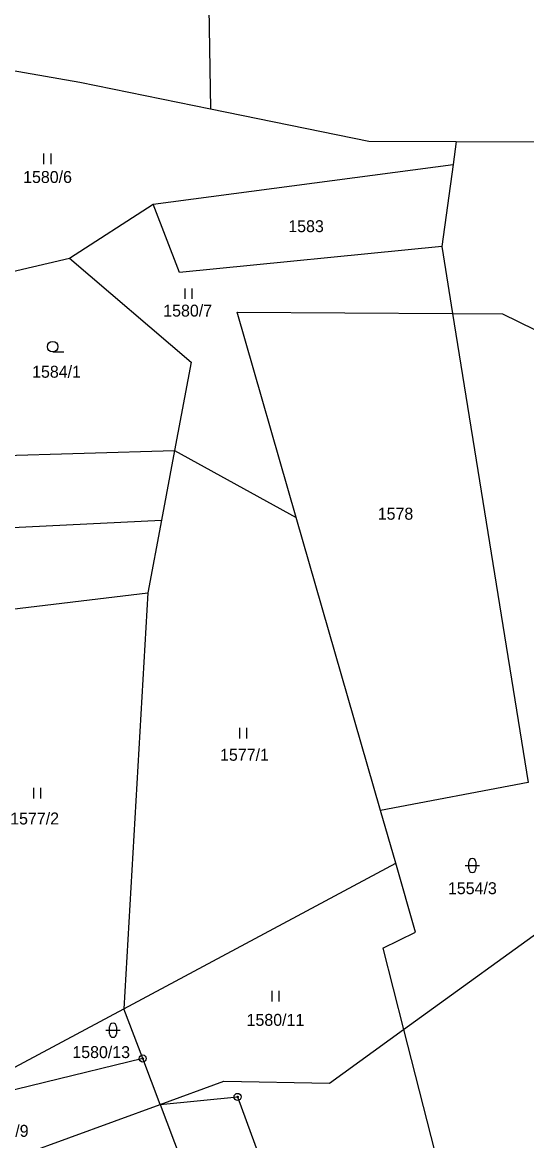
# Model space of a CAD drawing. Extents: x -445050 to -440454, y -1134563 to -1129741.
# Drawn here: x -442586.8 to -442515, y -1132305.3 to -1132146.1 of the extents above; entities that cross this region are included whole.
import ezdxf

# ---------------------------------------------------------------- set-up
doc = ezdxf.new("R2010")
doc.units = 0
for name, color, linetype in [('Vrstva 1', 7, 'Continuous'), ('Vrstva 18', 7, 'Continuous'), ('Vrstva 24', 7, 'Continuous'), ('Vrstva 25', 7, 'Continuous')]:
    doc.layers.add(name, color=color, linetype=linetype)

msp = doc.modelspace()

# ---------------------------------------------------------------- linework, layer by layer
at = {"layer": 'Vrstva 1'}
msp.add_line((-442525.04, -1132163.08), (-442509.94, -1132163.14), dxfattribs=at)
for points in [[(-442560.28, -1132144.07), (-442560.02, -1132158.43)], [(-442612.12, -1132148.81), (-442578.64, -1132154.62)], [(-442578.64, -1132154.62), (-442560.02, -1132158.43)], [(-442560.02, -1132158.43), (-442537.49, -1132163.03)], [(-442537.49, -1132163.03), (-442525.04, -1132163.08)], [(-442525.04, -1132163.08), (-442525.48, -1132166.35)], [(-442568.21, -1132172), (-442525.48, -1132166.35)], [(-442525.48, -1132166.35), (-442527.08, -1132178.05)], [(-442580.11, -1132179.71), (-442568.21, -1132172)], [(-442564.44, -1132181.73), (-442568.21, -1132172)], [(-442527.08, -1132178.05), (-442564.44, -1132181.73)], [(-442527.08, -1132178.05), (-442525.55, -1132187.56)], [(-442593.76, -1132182.86), (-442580.11, -1132179.71)], [(-442580.11, -1132179.71), (-442562.79, -1132194.5)], [(-442547.82, -1132216.6), (-442556.25, -1132187.37)], [(-442556.25, -1132187.37), (-442525.55, -1132187.56)], [(-442525.55, -1132187.56), (-442518.42, -1132187.61)], [(-442525.55, -1132187.56), (-442514.77, -1132254.31)], [(-442518.42, -1132187.61), (-442507.11, -1132193.16)], [(-442562.79, -1132194.5), (-442565.15, -1132207.06)], [(-442603.8, -1132208.19), (-442565.15, -1132207.06)], [(-442565.15, -1132207.06), (-442567.01, -1132216.98)], [(-442565.15, -1132207.06), (-442547.82, -1132216.6)], [(-442535.8, -1132258.33), (-442547.82, -1132216.6)], [(-442616.35, -1132219.39), (-442567.01, -1132216.98)], [(-442567.01, -1132216.98), (-442568.95, -1132227.32)], [(-442590.75, -1132229.95), (-442568.95, -1132227.32)], [(-442568.95, -1132227.32), (-442572.37, -1132286.52)], [(-442514.77, -1132254.31), (-442535.8, -1132258.33)], [(-442533.64, -1132265.82), (-442535.8, -1132258.33)], [(-442572.37, -1132286.52), (-442533.64, -1132265.82)], [(-442530.81, -1132275.65), (-442533.64, -1132265.82)], [(-442532.53, -1132289.48), (-442509.81, -1132273.06)], [(-442535.49, -1132277.89), (-442530.81, -1132275.65)], [(-442535.49, -1132277.89), (-442532.53, -1132289.48)], [(-442596.72, -1132299.53), (-442572.37, -1132286.52)], [(-442569.69, -1132293.61), (-442572.37, -1132286.52)], [(-442543.07, -1132297.1), (-442532.53, -1132289.48)], [(-442532.53, -1132289.48), (-442515.83, -1132354.84)], [(-442569.69, -1132293.61), (-442611.76, -1132303.88)], [(-442567.21, -1132300.16), (-442569.69, -1132293.61)], [(-442567.21, -1132300.16), (-442558.12, -1132296.85)], [(-442558.12, -1132296.85), (-442543.07, -1132297.1)], [(-442567.21, -1132300.16), (-442556.18, -1132299.07)], [(-442556.18, -1132299.07), (-442535.07, -1132356.7)], [(-442586.72, -1132307.27), (-442567.21, -1132300.16)], [(-442567.21, -1132300.16), (-442545.15, -1132358.52)]]:
    msp.add_lwpolyline(points, dxfattribs=at)
at = {"layer": 'Vrstva 24'}
for centre, radius in [((-442569.69, -1132293.61), 0.5), ((-442569.69, -1132293.61), 0.1), ((-442556.18, -1132299.07), 0.5), ((-442556.18, -1132299.07), 0.1)]:
    msp.add_circle(centre, radius, dxfattribs=at)
at = {"layer": 'Vrstva 25'}
for p, q in [((-442583.75, -1132166.29), (-442583.75, -1132164.79)), ((-442582.75, -1132166.29), (-442582.75, -1132164.79)), ((-442563.65, -1132185.49), (-442563.65, -1132183.99)), ((-442562.65, -1132185.49), (-442562.65, -1132183.99)), ((-442582.51, -1132193.04), (-442580.91, -1132193.04)), ((-442555.86, -1132248.04), (-442555.86, -1132246.54)), ((-442554.86, -1132248.04), (-442554.86, -1132246.54)), ((-442585.22, -1132256.58), (-442585.22, -1132255.08)), ((-442584.22, -1132256.58), (-442584.22, -1132255.08)), ((-442523.74, -1132266.13), (-442521.74, -1132266.13)), ((-442523.24, -1132266.63), (-442523.24, -1132265.63)), ((-442522.24, -1132265.63), (-442522.24, -1132266.63)), ((-442551.23, -1132285.5), (-442551.23, -1132284)), ((-442550.23, -1132285.5), (-442550.23, -1132284)), ((-442574.92, -1132289.59), (-442572.92, -1132289.59)), ((-442574.42, -1132290.09), (-442574.42, -1132289.09)), ((-442573.42, -1132289.09), (-442573.42, -1132290.09))]:
    msp.add_line(p, q, dxfattribs=at)
msp.add_circle((-442582.51, -1132192.29), 0.75, dxfattribs=at)
for centre, start, end in [((-442522.74, -1132265.63), 0, 180), ((-442522.74, -1132266.63), 180, 0), ((-442573.92, -1132289.09), 0, 180), ((-442573.92, -1132290.09), 180, 0)]:
    msp.add_arc(centre, 0.5, start, end, dxfattribs=at)

# ---------------------------------------------------------------- texts
at = {"layer": 'Vrstva 18'}
for s, p in [('1580/6', (-442586.72, -1132168.99)), ('1583', (-442548.95, -1132175.99)), ('1580/7', (-442566.76, -1132188.01)), ('1584/1', (-442585.44, -1132196.71)), ('1578', (-442536.21, -1132216.92)), ('1577/1', (-442558.67, -1132251.23)), ('1577/2', (-442588.56, -1132260.3)), ('1554/3', (-442526.21, -1132270.22)), ('1580/11', (-442554.89, -1132288.96)), ('1580/13', (-442579.71, -1132293.55)), ('1580/9', (-442592.9, -1132304.76))]:
    msp.add_text(s, height=1.7, dxfattribs=at).set_placement(p)

doc.saveas('drawing.dxf')
